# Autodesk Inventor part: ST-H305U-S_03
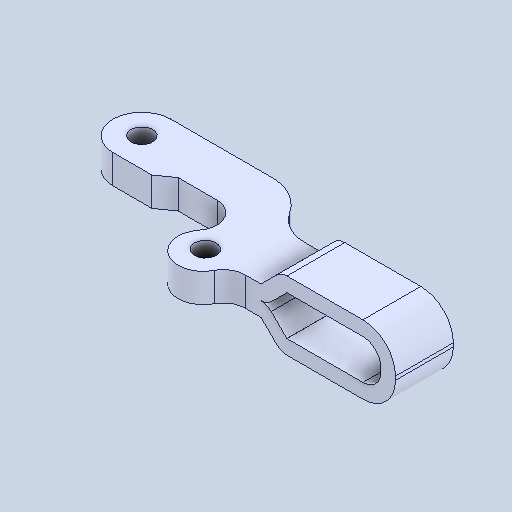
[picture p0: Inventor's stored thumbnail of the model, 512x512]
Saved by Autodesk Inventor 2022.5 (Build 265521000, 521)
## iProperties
Created: 2024-07
Part Number: ST-H305U-S_03
Material: 一般
Document SubType Name: Modeling
Designer: ImaoCorp
Density: 1 g/cm^3
Appearance: 既定
Author: ImaoCorp
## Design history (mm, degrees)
feature "ST-H305U-S_03"
node "ソリッド1"
